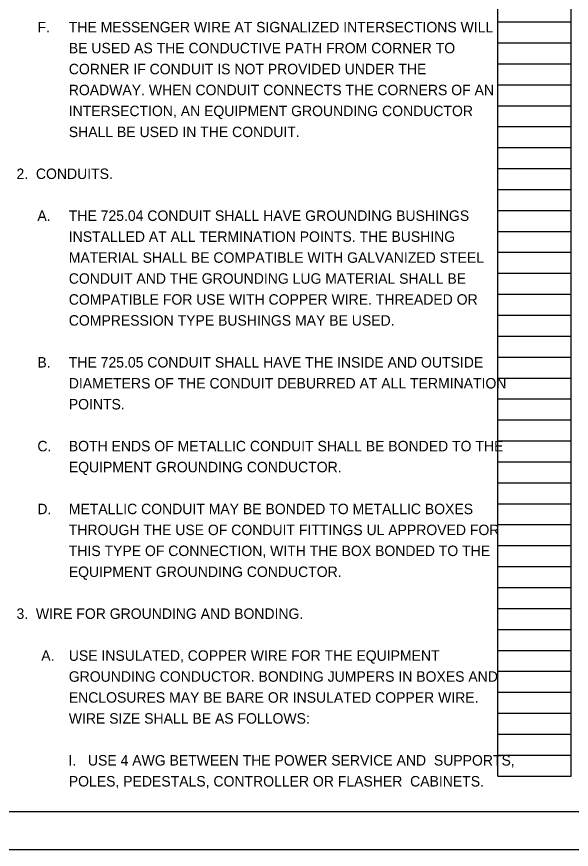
# Model space of a CAD drawing. Extents: x 0 to 34, y 0 to 22.
# Drawn here: x 17.24 to 24.66, y 0 to 11.13 of the extents above; entities that cross this region are included whole.
import ezdxf

# ---------------------------------------------------------------- set-up
doc = ezdxf.new("R2010")
doc.units = 0
for name, color, linetype in [('SH_Border', 7, 'Continuous'), ('SH_Cut_Line', 7, 'Continuous'), ('SH_Data', 7, 'Continuous'), ('SH_Text', 7, 'Continuous')]:
    doc.layers.add(name, color=color, linetype=linetype)

msp = doc.modelspace()

# ---------------------------------------------------------------- linework, layer by layer
at = {"layer": 'SH_Border'}
msp.add_lwpolyline([(1.5, 21.5), (33.5, 21.5), (33.5, 0.5), (1.5, 0.5)], close=True, dxfattribs=at)
at = {"layer": 'SH_Cut_Line'}
msp.add_lwpolyline([(0, 0), (34, 0), (34, 22), (0, 22)], close=True, dxfattribs=at)
at = {"layer": 'SH_Data'}
for p, q in [((23.68, 0.98), (23.68, 21.14)), ((24.66, 0.98), (24.66, 21.14)), ((23.68, 11.06), (24.66, 11.06)), ((23.68, 10.78), (24.66, 10.78)), ((23.68, 10.5), (24.66, 10.5)), ((23.68, 10.22), (24.66, 10.22)), ((23.68, 9.94), (24.66, 9.94)), ((23.68, 9.66), (24.66, 9.66)), ((23.68, 9.38), (24.66, 9.38)), ((23.68, 9.1), (24.66, 9.1)), ((23.68, 8.82), (24.66, 8.82)), ((23.68, 8.54), (24.66, 8.54)), ((23.68, 8.26), (24.66, 8.26)), ((23.68, 7.98), (24.66, 7.98)), ((23.68, 7.7), (24.66, 7.7)), ((23.68, 7.42), (24.66, 7.42)), ((23.68, 7.14), (24.66, 7.14)), ((23.68, 6.86), (24.66, 6.86)), ((23.68, 6.58), (24.66, 6.58)), ((23.68, 6.3), (24.66, 6.3)), ((23.68, 6.02), (24.66, 6.02)), ((23.68, 5.74), (24.66, 5.74)), ((23.68, 5.46), (24.66, 5.46)), ((23.68, 5.18), (24.66, 5.18)), ((23.68, 4.9), (24.66, 4.9)), ((23.68, 4.62), (24.66, 4.62)), ((23.68, 4.34), (24.66, 4.34)), ((23.68, 4.06), (24.66, 4.06)), ((23.68, 3.78), (24.66, 3.78)), ((23.68, 3.5), (24.66, 3.5)), ((23.68, 3.22), (24.66, 3.22)), ((23.68, 2.94), (24.66, 2.94)), ((23.68, 2.66), (24.66, 2.66)), ((23.68, 2.38), (24.66, 2.38)), ((23.68, 2.1), (24.66, 2.1)), ((23.68, 1.82), (24.66, 1.82)), ((23.68, 1.54), (24.66, 1.54)), ((23.68, 1.26), (24.66, 1.26)), ((23.68, 0.98), (24.66, 0.98))]:
    msp.add_line(p, q, dxfattribs=at)

# ---------------------------------------------------------------- texts
at = {"layer": 'SH_Text'}
for s, p in [('F.', (17.52, 10.92)), ('THE MESSENGER WIRE AT SIGNALIZED INTERSECTIONS WILL ', (17.94, 10.92)), ('BE USED AS THE CONDUCTIVE PATH FROM CORNER TO ', (17.94, 10.64)), ('CORNER IF CONDUIT IS NOT PROVIDED UNDER THE ', (17.94, 10.36)), ('ROADWAY. WHEN CONDUIT CONNECTS THE CORNERS OF AN ', (17.94, 10.08)), ('INTERSECTION, AN EQUIPMENT GROUNDING CONDUCTOR ', (17.94, 9.8)), ('SHALL BE USED IN THE CONDUIT.', (17.94, 9.52)), ('2.  CONDUITS.', (17.24, 8.96)), ('A.', (17.52, 8.4)), ('THE 725.04 CONDUIT SHALL HAVE GROUNDING BUSHINGS ', (17.94, 8.4)), ('INSTALLED AT ALL TERMINATION POINTS. THE BUSHING ', (17.94, 8.12)), ('MATERIAL SHALL BE COMPATIBLE WITH GALVANIZED STEEL ', (17.94, 7.84)), ('CONDUIT AND THE GROUNDING LUG MATERIAL SHALL BE ', (17.94, 7.56)), ('COMPATIBLE FOR USE WITH COPPER WIRE. THREADED OR ', (17.94, 7.28)), ('COMPRESSION TYPE BUSHINGS MAY BE USED.', (17.94, 7)), ('B.', (17.52, 6.44)), ('THE 725.05 CONDUIT SHALL HAVE THE INSIDE AND OUTSIDE ', (17.94, 6.44)), ('DIAMETERS OF THE CONDUIT DEBURRED AT ALL TERMINATION ', (17.94, 6.16)), ('POINTS.', (17.94, 5.88)), ('C.', (17.52, 5.32)), ('BOTH ENDS OF METALLIC CONDUIT SHALL BE BONDED TO THE ', (17.94, 5.32)), ('EQUIPMENT GROUNDING CONDUCTOR.', (17.94, 5.04)), ('D.', (17.52, 4.48)), ('METALLIC CONDUIT MAY BE BONDED TO METALLIC BOXES ', (17.94, 4.48)), ('THROUGH THE USE OF CONDUIT FITTINGS UL APPROVED FOR ', (17.94, 4.2)), ('THIS TYPE OF CONNECTION, WITH THE BOX BONDED TO THE ', (17.94, 3.92)), ('EQUIPMENT GROUNDING CONDUCTOR.', (17.94, 3.64)), ('3.  WIRE FOR GROUNDING AND BONDING.', (17.24, 3.08)), (' A.', (17.52, 2.52)), ('USE INSULATED, COPPER WIRE FOR THE EQUIPMENT ', (17.94, 2.52)), ('GROUNDING CONDUCTOR. BONDING JUMPERS IN BOXES AND ', (17.94, 2.24)), ('ENCLOSURES MAY BE BARE OR INSULATED COPPER WIRE. ', (17.94, 1.96)), ('WIRE SIZE SHALL BE AS FOLLOWS:', (17.94, 1.68)), ('        I.   USE 4 AWG BETWEEN THE POWER SERVICE AND  SUPPORTS, ', (17.52, 1.12)), ('POLES, PEDESTALS, CONTROLLER OR FLASHER  CABINETS.', (17.94, 0.84))]:
    msp.add_text(s, height=0.14, dxfattribs=at).set_placement(p)

doc.saveas('drawing.dxf')
